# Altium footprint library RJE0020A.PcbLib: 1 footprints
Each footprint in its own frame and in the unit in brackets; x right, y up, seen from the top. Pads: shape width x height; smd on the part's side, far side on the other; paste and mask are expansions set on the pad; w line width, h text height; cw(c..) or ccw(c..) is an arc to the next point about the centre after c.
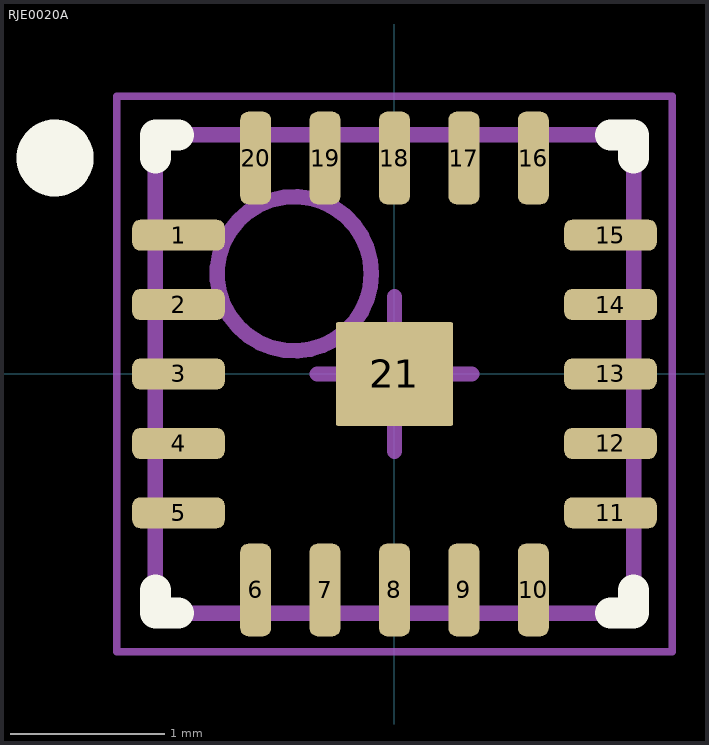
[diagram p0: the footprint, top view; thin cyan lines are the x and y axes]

## RJE0020A [mm] "PQFN, 20-Leads, Body 3.00x3.00mm, Pitch 0.45mm, Thermal Pad 0.76x0.68mm, IPC Medium Density"
height 1
pads (21):
  rrect50% 0.6x0.2 smd paste+0.05: 1(-1.4,0.9) 2(-1.4,0.45) 3(-1.4,0) 4(-1.4,-0.45) 5(-1.4,-0.9) 11(1.4,-0.9) 12(1.4,-0.45) 13(1.4,0) 14(1.4,0.45) 15(1.4,0.9)
  rrect50% 0.2x0.6 smd paste+0.05: 6(-0.9,-1.4) 7(-0.45,-1.4) 8(0,-1.4) 9(0.45,-1.4) 10(0.9,-1.4) 16(0.9,1.4) 17(0.45,1.4) 18(0,1.4) 19(-0.45,1.4) 20(-0.9,1.4)
  rrect5% 0.76x0.675 smd paste+0.05: 21(0,0)
Top Overlay:
  circle w0.25: c-2.2,1.4 r0.125
  lines w0.2: -1.55,-1.4 -1.55,-1.55 -1.4,-1.55 ; -1.55,1.4 -1.55,1.55 -1.4,1.55 ; 1.4,-1.55 1.55,-1.55 1.55,-1.4 ; 1.4,1.55 1.55,1.55 1.55,1.4
Mechanical 13:
  circle w0.1: c-0.65,0.65 r0.5
  lines w0.1: -1.55,-1.55 1.55,-1.55 1.55,1.55 -1.55,1.55 -1.55,-1.55
Mechanical 15:
  lines w0.05: -1.8,-1.8 1.8,-1.8 1.8,1.8 -1.8,1.8 -1.8,-1.8
  lines w0.1: -0.5,0 0.5,0 ; 0,-0.5 0,0.5
3D body "RJE0020A.step": height 1, standoff 0, extent -1.55,-1.55 1.55,1.55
